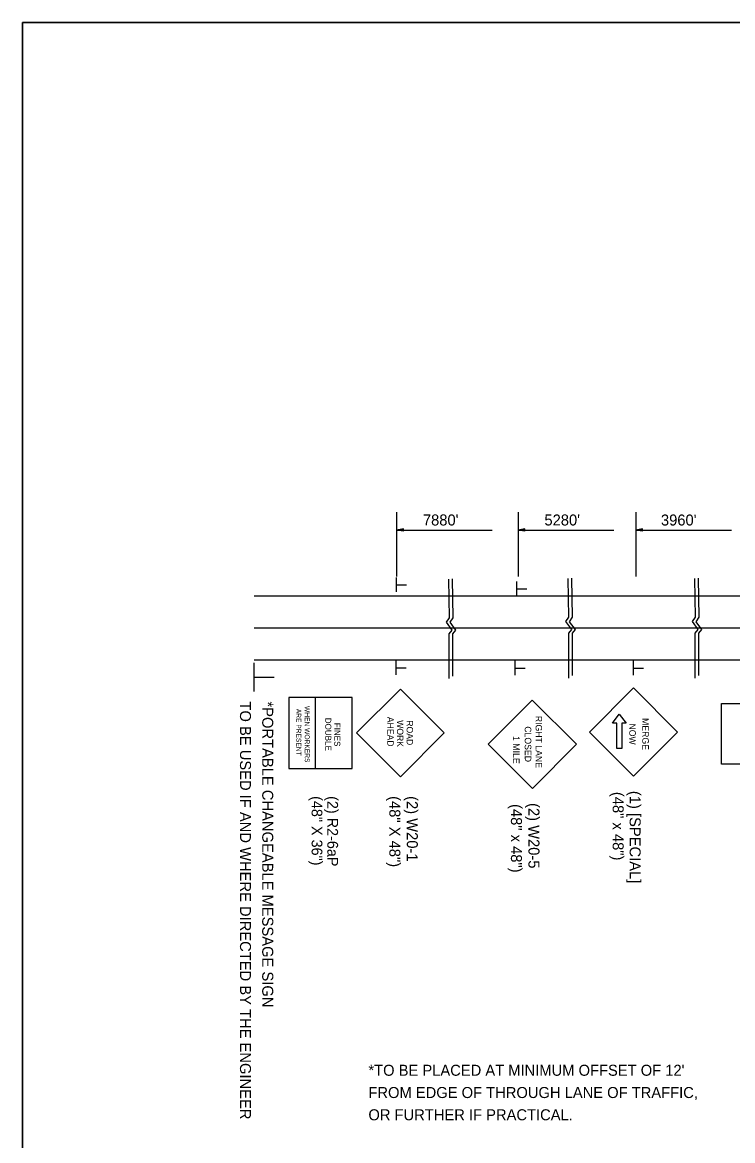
# Model space of a CAD drawing. Extents: x 1374027 to 1374537, y 380415 to 381405.
# Drawn here: x 1374027.1 to 1374065.8, y 380904.2 to 380965.2 of the extents above; entities that cross this region are included whole.
import ezdxf

# ---------------------------------------------------------------- set-up
doc = ezdxf.new("R2010")
doc.units = 0
doc.layers.add('Default', color=7, linetype='Continuous')
doc.layers.add('DSN_DRFT_Junk-No-Plot', color=7, linetype='Continuous')

msp = doc.modelspace()

# ---------------------------------------------------------------- linework, layer by layer
at = {"layer": 'Default'}
for p, q in [((1374047.478, 380938.487), (1374047.478, 380934.966)), ((1374054.102, 380938.487), (1374054.102, 380934.966)), ((1374060.518, 380938.487), (1374060.518, 380934.966)), ((1374047.853, 380937.564), (1374047.478, 380937.508)), ((1374047.853, 380937.554), (1374047.541, 380937.508)), ((1374047.853, 380937.545), (1374047.605, 380937.508)), ((1374047.853, 380937.535), (1374047.668, 380937.508)), ((1374047.853, 380937.451), (1374047.853, 380937.564)), ((1374054.477, 380937.564), (1374054.102, 380937.508)), ((1374054.477, 380937.554), (1374054.165, 380937.508)), ((1374054.477, 380937.545), (1374054.229, 380937.508)), ((1374054.477, 380937.535), (1374054.292, 380937.508)), ((1374054.477, 380937.451), (1374054.477, 380937.564)), ((1374060.893, 380937.564), (1374060.518, 380937.508)), ((1374060.893, 380937.554), (1374060.581, 380937.508)), ((1374060.893, 380937.545), (1374060.645, 380937.508)), ((1374060.893, 380937.535), (1374060.708, 380937.508)), ((1374060.893, 380937.451), (1374060.893, 380937.564)), ((1374047.478, 380937.508), (1374052.697, 380937.508)), ((1374047.853, 380937.451), (1374047.478, 380937.508)), ((1374047.853, 380937.461), (1374047.541, 380937.508)), ((1374047.853, 380937.47), (1374047.605, 380937.508)), ((1374047.853, 380937.48), (1374047.668, 380937.508)), ((1374047.853, 380937.526), (1374047.731, 380937.508)), ((1374047.853, 380937.489), (1374047.731, 380937.508)), ((1374047.853, 380937.516), (1374047.794, 380937.508)), ((1374047.853, 380937.499), (1374047.794, 380937.508)), ((1374054.102, 380937.508), (1374059.321, 380937.508)), ((1374054.477, 380937.451), (1374054.102, 380937.508)), ((1374054.477, 380937.461), (1374054.165, 380937.508)), ((1374054.477, 380937.47), (1374054.229, 380937.508)), ((1374054.477, 380937.48), (1374054.292, 380937.508)), ((1374054.477, 380937.526), (1374054.355, 380937.508)), ((1374054.477, 380937.489), (1374054.355, 380937.508)), ((1374054.477, 380937.516), (1374054.418, 380937.508)), ((1374054.477, 380937.499), (1374054.418, 380937.508)), ((1374060.518, 380937.508), (1374065.737, 380937.508)), ((1374060.893, 380937.451), (1374060.518, 380937.508)), ((1374060.893, 380937.461), (1374060.581, 380937.508)), ((1374060.893, 380937.47), (1374060.645, 380937.508)), ((1374060.893, 380937.48), (1374060.708, 380937.508)), ((1374060.893, 380937.526), (1374060.771, 380937.508)), ((1374060.893, 380937.489), (1374060.771, 380937.508)), ((1374060.893, 380937.516), (1374060.834, 380937.508)), ((1374060.893, 380937.499), (1374060.834, 380937.508)), ((1374047.478, 380934.13), (1374047.478, 380934.913)), ((1374047.49, 380934.519), (1374048.024, 380934.519)), ((1374054.04, 380933.922), (1374054.04, 380934.704)), ((1374039.716, 380933.916), (1374181.443, 380933.916)), ((1374054.052, 380934.311), (1374054.586, 380934.311)), ((1374039.716, 380932.177), (1374181.443, 380932.177)), ((1374039.716, 380930.439), (1374181.443, 380930.439)), ((1374039.716, 380928.702), (1374039.716, 380930.267)), ((1374047.469, 380929.612), (1374047.469, 380930.394)), ((1374053.943, 380929.596), (1374053.943, 380930.378)), ((1374060.403, 380929.59), (1374060.403, 380930.372)), ((1374047.48, 380930.001), (1374048.014, 380930.001)), ((1374053.955, 380929.985), (1374054.489, 380929.985)), ((1374060.415, 380929.979), (1374060.949, 380929.979)), ((1374039.739, 380929.48), (1374040.807, 380929.48)), ((1374045.301, 380926.448), (1374047.689, 380928.838)), ((1374050.079, 380926.448), (1374047.689, 380928.838)), ((1374057.996, 380926.492), (1374060.397, 380928.902)), ((1374062.805, 380926.5), (1374060.397, 380928.902)), ((1374043.066, 380924.517), (1374043.066, 380928.379)), ((1374052.479, 380925.829), (1374054.881, 380928.239)), ((1374057.289, 380925.837), (1374054.881, 380928.239)), ((1374059.246, 380926.977), (1374059.621, 380927.464)), ((1374059.621, 380927.464), (1374059.996, 380926.977)), ((1374059.481, 380926.977), (1374059.246, 380926.977)), ((1374059.481, 380925.598), (1374059.481, 380926.977)), ((1374059.762, 380926.977), (1374059.762, 380925.598)), ((1374059.996, 380926.977), (1374059.762, 380926.977)), ((1374047.689, 380924.057), (1374045.301, 380926.448)), ((1374047.689, 380924.057), (1374050.079, 380926.448)), ((1374060.406, 380924.09), (1374057.996, 380926.492)), ((1374060.406, 380924.09), (1374062.805, 380926.5)), ((1374054.889, 380923.427), (1374052.479, 380925.829)), ((1374054.889, 380923.427), (1374057.289, 380925.837)), ((1374059.762, 380925.598), (1374059.481, 380925.598))]:
    msp.add_line(p, q, dxfattribs=at)
for points in [[(1374050.309, 380934.832), (1374050.341, 380932.729), (1374050.179, 380932.487), (1374050.495, 380932.054), (1374050.329, 380931.854), (1374050.328, 380929.409)], [(1374050.509, 380934.851), (1374050.541, 380932.72), (1374050.379, 380932.479), (1374050.695, 380932.046), (1374050.529, 380931.846), (1374050.528, 380929.549)], [(1374056.827, 380934.865), (1374056.859, 380932.762), (1374056.697, 380932.52), (1374057.013, 380932.088), (1374056.847, 380931.888), (1374056.846, 380929.442)], [(1374057.027, 380934.884), (1374057.059, 380932.754), (1374056.897, 380932.512), (1374057.213, 380932.079), (1374057.047, 380931.879), (1374057.046, 380929.583)], [(1374063.728, 380934.865), (1374063.76, 380932.762), (1374063.598, 380932.52), (1374063.914, 380932.088), (1374063.747, 380931.888), (1374063.747, 380929.442)], [(1374063.927, 380934.884), (1374063.96, 380932.754), (1374063.797, 380932.512), (1374064.114, 380932.079), (1374063.947, 380931.879), (1374063.947, 380929.583)]]:
    msp.add_lwpolyline(points, dxfattribs=at)
for points in [[(1374045.068, 380928.379), (1374041.616, 380928.379), (1374041.616, 380924.517), (1374045.068, 380924.517)], [(1374069.384, 380924.744), (1374065.202, 380924.744), (1374065.202, 380928.062), (1374069.384, 380928.062)]]:
    msp.add_lwpolyline(points, close=True, dxfattribs=at)
at = {"layer": 'DSN_DRFT_Junk-No-Plot'}
for points in [[(1374027.083, 380965.174), (1374197.083, 380965.174), (1374197.083, 380855.174), (1374027.083, 380855.174)], [(1374027.083, 380965.174), (1374027.083, 380855.174), (1374197.083, 380855.174), (1374197.083, 380965.174)]]:
    msp.add_lwpolyline(points, close=True, dxfattribs=at)

# ---------------------------------------------------------------- texts
at = {"layer": 'Default'}
for s, p in [("7880'", (1374048.918, 380937.754)), ("5280'", (1374055.542, 380937.754)), ("3960'", (1374061.895, 380937.753)), ("*TO BE PLACED AT MINIMUM OFFSET OF 12'", (1374045.947, 380907.765)), ('FROM EDGE OF THROUGH LANE OF TRAFFIC,', (1374045.947, 380906.552)), ('OR FURTHER IF PRACTICAL.', (1374045.947, 380905.339))]:
    msp.add_text(s, height=0.6, dxfattribs=at).set_placement(p)
for s, height, rotation, p in [('TO BE USED IF AND WHERE DIRECTED BY THE ENGINEER', 0.6, 270, (1374038.946, 380928.164)), ('*PORTABLE CHANGEABLE MESSAGE SIGN', 0.6, 270, (1374040.159, 380928.164)), ('WHEN WORKERS', 0.26221, 270, (1374042.48, 380927.917)), ('ARE PRESENT', 0.26221, 270, (1374042.02, 380927.765)), ('DOUBLE', 0.3278, 270, (1374043.596, 380927.274)), (' AHEAD', 0.3522, 270.00057, (1374046.973, 380927.46)), ('RIGHT LANE', 0.3544, 270.10045, (1374055.059, 380927.382)), ('MERGE', 0.3544, 270.10045, (1374060.877, 380927.258)), ('FINES', 0.3278, 270, (1374044.088, 380927.003)), ('WORK', 0.352, 270.00004, (1374047.501, 380927.145)), ('ROAD', 0.3521, 270.00045, (1374048.03, 380927.138)), ('CLOSED', 0.3543, 270.10034, (1374054.47, 380926.811)), ('NOW', 0.3543, 270.10034, (1374060.168, 380926.965)), ('1 MILE', 0.3567, 270.00057, (1374053.829, 380926.28)), ('(48" X 36")', 0.5862, 270, (1374042.851, 380923.006)), ('(2) R2-6aP', 0.5862, 270, (1374043.707, 380923.006)), ('(48" X 48")', 0.6, 270, (1374047.09, 380923.006)), ('(2) W20-1', 0.6, 270, (1374048.041, 380923.006)), ('(48" x 48")', 0.6, 270, (1374059.263, 380923.237)), ('(1) [SPECIAL]', 0.6, 270, (1374060.188, 380923.291)), ('(48" x 48")', 0.6, 270, (1374053.716, 380922.574)), ('(2) W20-5', 0.6, 270, (1374054.671, 380922.628))]:
    msp.add_text(s, height=height, rotation=rotation, dxfattribs=at).set_placement(p)

doc.saveas('drawing.dxf')
